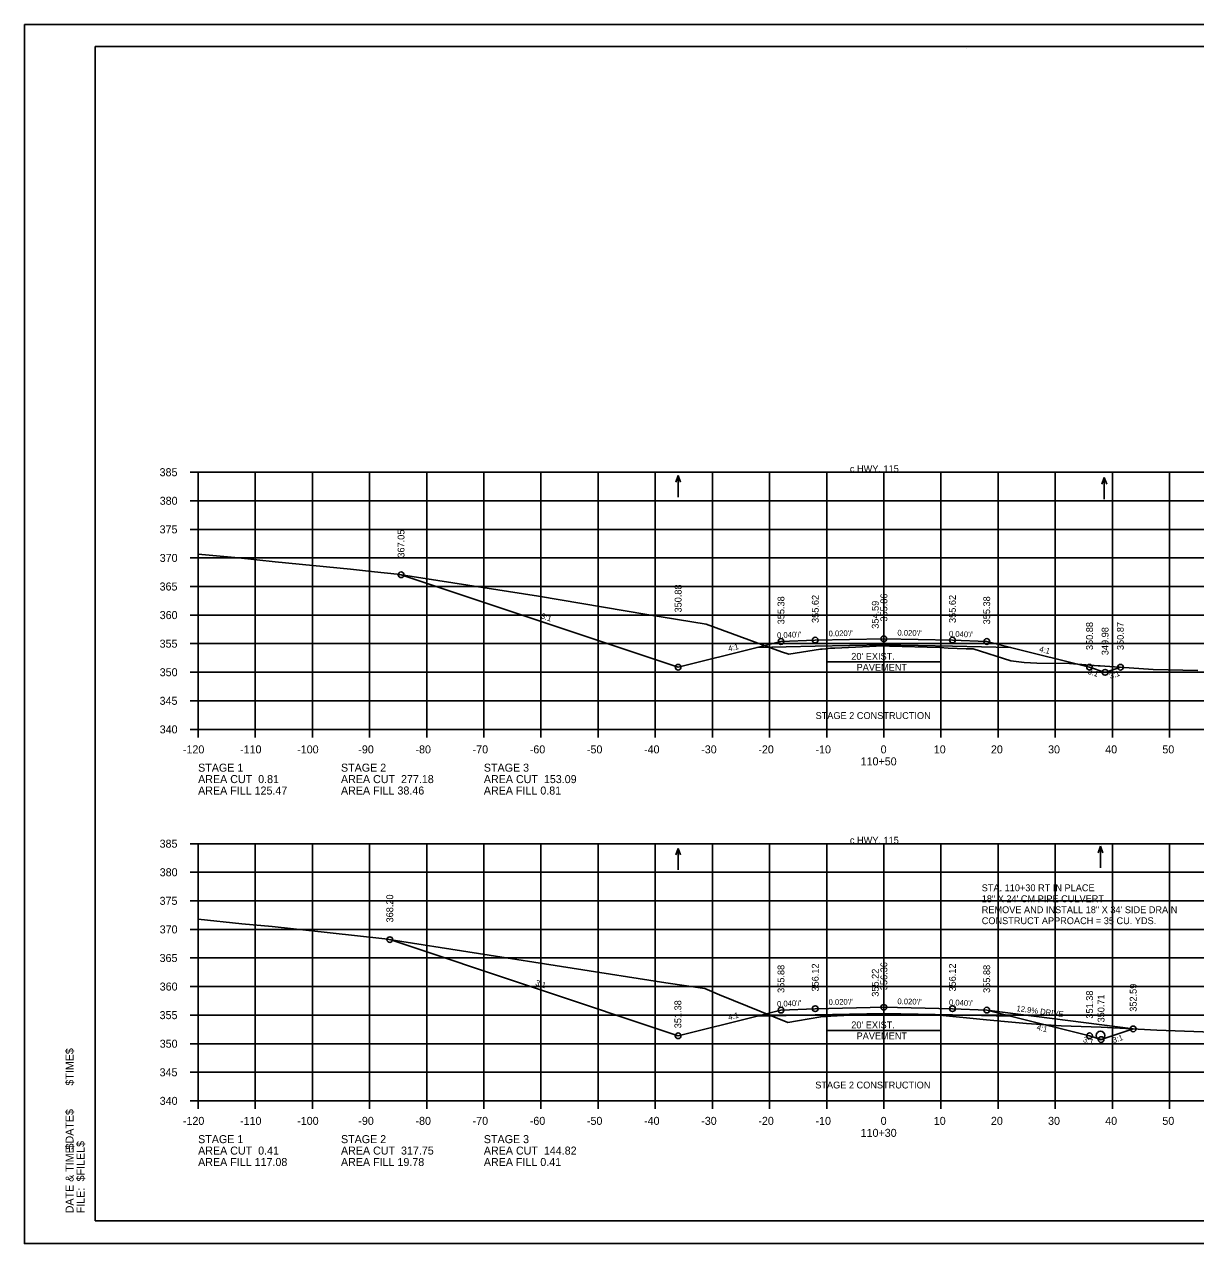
# Model space of a CAD drawing. Extents: x 1630712 to 1632516, y 782146 to 785403.
# Drawn here: x 1632182.6 to 1632387.5, y 784123.3 to 784336.6 of the extents above; entities that cross this region are included whole.
import ezdxf

# ---------------------------------------------------------------- set-up
doc = ezdxf.new("R2010")
doc.units = 0
for name, color, linetype in [('Default', 7, 'Continuous'), ('Notes', 7, 'Continuous'), ('R_Alt Surface', 7, 'Continuous'), ('R_Axis', 7, 'Continuous'), ('R_Axis Annot', 7, 'Continuous'), ('R_Border', 7, 'Continuous'), ('R_Culvert', 7, 'Continuous'), ('R_Culvert Annot', 7, 'Continuous'), ('R_Culvert Disable', 7, 'Continuous'), ('R_Exist Surface', 7, 'Continuous'), ('R_Fin Surface', 7, 'Continuous'), ('R_Grid', 7, 'Continuous'), ('R_No Plot', 7, 'Continuous'), ('R_Water Annot', 7, 'Continuous'), ('R_Xsect Elev', 7, 'Continuous'), ('R_Xsect Slope', 7, 'Continuous')]:
    doc.layers.add(name, color=color, linetype=linetype)

msp = doc.modelspace()

# ---------------------------------------------------------------- linework, layer by layer
at = {"layer": 'Notes'}
for p, q in [((1632322.96, 784223.41), (1632322.96, 784226.81)), ((1632322.96, 784225.11), (1632342.96, 784225.11)), ((1632342.96, 784223.41), (1632342.96, 784226.81)), ((1632322.96, 784158.92), (1632322.96, 784162.32)), ((1632342.96, 784158.92), (1632342.96, 784162.32)), ((1632322.96, 784160.62), (1632342.96, 784160.62))]:
    msp.add_line(p, q, dxfattribs=at)
at = {"layer": 'R_Alt Surface'}
for points in [[(1632310.78, 784227.63), (1632320.96, 784227.83), (1632332.96, 784228.07), (1632344.96, 784227.83), (1632355.15, 784227.63)], [(1632310.78, 784163.13), (1632320.96, 784163.33), (1632332.96, 784163.57), (1632344.96, 784163.33), (1632355.15, 784163.13)]]:
    msp.add_lwpolyline(points, dxfattribs=at)
at = {"layer": 'R_Axis'}
for p, q in [((1632211.56, 784258.29), (1632212.96, 784258.29)), ((1632212.96, 784213.29), (1632212.96, 784258.29)), ((1632211.56, 784253.29), (1632212.96, 784253.29)), ((1632211.56, 784248.29), (1632212.96, 784248.29)), ((1632211.56, 784243.29), (1632212.96, 784243.29)), ((1632211.56, 784238.29), (1632212.96, 784238.29)), ((1632211.56, 784233.29), (1632212.96, 784233.29)), ((1632211.56, 784228.29), (1632212.96, 784228.29)), ((1632211.56, 784223.29), (1632212.96, 784223.29)), ((1632211.56, 784218.29), (1632212.96, 784218.29)), ((1632211.56, 784213.29), (1632212.96, 784213.29)), ((1632212.96, 784213.29), (1632492.96, 784213.29)), ((1632212.96, 784211.89), (1632212.96, 784213.29)), ((1632222.96, 784211.89), (1632222.96, 784213.29)), ((1632232.96, 784211.89), (1632232.96, 784213.29)), ((1632242.96, 784211.89), (1632242.96, 784213.29)), ((1632252.96, 784211.89), (1632252.96, 784213.29)), ((1632262.96, 784211.89), (1632262.96, 784213.29)), ((1632272.96, 784211.89), (1632272.96, 784213.29)), ((1632282.96, 784211.89), (1632282.96, 784213.29)), ((1632292.96, 784211.89), (1632292.96, 784213.29)), ((1632302.96, 784211.89), (1632302.96, 784213.29)), ((1632312.96, 784211.89), (1632312.96, 784213.29)), ((1632322.96, 784211.89), (1632322.96, 784213.29)), ((1632332.96, 784211.89), (1632332.96, 784213.29)), ((1632342.96, 784211.89), (1632342.96, 784213.29)), ((1632352.96, 784211.89), (1632352.96, 784213.29)), ((1632362.96, 784211.89), (1632362.96, 784213.29)), ((1632372.96, 784211.89), (1632372.96, 784213.29)), ((1632382.96, 784211.89), (1632382.96, 784213.29)), ((1632211.56, 784193.29), (1632212.96, 784193.29)), ((1632212.96, 784148.29), (1632212.96, 784193.29)), ((1632211.56, 784188.29), (1632212.96, 784188.29)), ((1632211.56, 784183.29), (1632212.96, 784183.29)), ((1632211.56, 784178.29), (1632212.96, 784178.29)), ((1632211.56, 784173.29), (1632212.96, 784173.29)), ((1632211.56, 784168.29), (1632212.96, 784168.29)), ((1632211.56, 784163.29), (1632212.96, 784163.29)), ((1632211.56, 784158.29), (1632212.96, 784158.29)), ((1632211.56, 784153.29), (1632212.96, 784153.29)), ((1632211.56, 784148.29), (1632212.96, 784148.29)), ((1632212.96, 784148.29), (1632492.96, 784148.29)), ((1632212.96, 784146.89), (1632212.96, 784148.29)), ((1632222.96, 784146.89), (1632222.96, 784148.29)), ((1632232.96, 784146.89), (1632232.96, 784148.29)), ((1632242.96, 784146.89), (1632242.96, 784148.29)), ((1632252.96, 784146.89), (1632252.96, 784148.29)), ((1632262.96, 784146.89), (1632262.96, 784148.29)), ((1632272.96, 784146.89), (1632272.96, 784148.29)), ((1632282.96, 784146.89), (1632282.96, 784148.29)), ((1632292.96, 784146.89), (1632292.96, 784148.29)), ((1632302.96, 784146.89), (1632302.96, 784148.29)), ((1632312.96, 784146.89), (1632312.96, 784148.29)), ((1632322.96, 784146.89), (1632322.96, 784148.29)), ((1632332.96, 784146.89), (1632332.96, 784148.29)), ((1632342.96, 784146.89), (1632342.96, 784148.29)), ((1632352.96, 784146.89), (1632352.96, 784148.29)), ((1632362.96, 784146.89), (1632362.96, 784148.29)), ((1632372.96, 784146.89), (1632372.96, 784148.29)), ((1632382.96, 784146.89), (1632382.96, 784148.29))]:
    msp.add_line(p, q, dxfattribs=at)
at = {"layer": 'R_Border'}
for p, q in [((1632194.96, 784332.75), (1632511.14, 784332.75)), ((1632194.96, 784127.29), (1632194.96, 784332.75)), ((1632347.48, 784332.49), (1632347.48, 784332.49)), ((1632347.48, 784332.49), (1632347.48, 784332.49)), ((1632511.14, 784127.29), (1632194.96, 784127.29))]:
    msp.add_line(p, q, dxfattribs=at)
at = {"layer": 'R_Culvert'}
for radius in [0.755, 0.75]:
    msp.add_circle((1632370.89, 784159.74), radius, dxfattribs=at)
at = {"layer": 'R_Culvert Disable'}
for radius in [0.755, 0.75]:
    msp.add_circle((1632370.89, 784159.74), radius, dxfattribs=at)
at = {"layer": 'R_Exist Surface'}
for points in [[(1632212.96, 784243.96), (1632220.03, 784243.28), (1632226.44, 784242.58), (1632239.62, 784241.33), (1632243.82, 784240.88), (1632247.81, 784240.44), (1632272.55, 784236.59), (1632291.5, 784233.39), (1632301.87, 784231.7), (1632315.07, 784226.86), (1632316.35, 784226.44), (1632321.88, 784227.3), (1632322.09, 784227.34), (1632322.17, 784227.35), (1632322.78, 784227.4), (1632323.63, 784227.49), (1632324.39, 784227.52), (1632332.83, 784227.89), (1632333.92, 784227.86), (1632342.73, 784227.64), (1632344.19, 784227.51), (1632347.35, 784227.39), (1632348.61, 784227.36), (1632355.18, 784225.3), (1632357.52, 784224.99), (1632359.73, 784224.88), (1632365.43, 784224.83), (1632370.45, 784224.42), (1632370.58, 784224.42), (1632370.79, 784224.41), (1632380.08, 784223.79), (1632387.91, 784223.59)], [(1632212.96, 784180.11), (1632220.61, 784179.28), (1632225.91, 784178.77), (1632236.04, 784177.67), (1632245.66, 784176.63), (1632294.82, 784168.97), (1632301.61, 784167.96), (1632304.18, 784166.85), (1632316.14, 784161.99), (1632317.87, 784162.31), (1632321.92, 784163), (1632322.78, 784163.06), (1632323.66, 784163.13), (1632327.07, 784163.28), (1632332.89, 784163.52), (1632339.02, 784163.36), (1632342.72, 784163.27), (1632350.92, 784162.44), (1632354.69, 784162.12), (1632357.9, 784161.85), (1632363.99, 784161.44), (1632370.98, 784161.16), (1632380.71, 784160.67), (1632390.39, 784160.33)]]:
    msp.add_lwpolyline(points, dxfattribs=at)
at = {"layer": 'R_Fin Surface'}
msp.add_line((1632350.96, 784164.18), (1632376.6, 784160.88), dxfattribs=at)
for points in [[(1632248.47, 784240.34), (1632296.96, 784224.17), (1632310.78, 784227.63), (1632314.96, 784228.67), (1632320.96, 784228.91), (1632332.96, 784229.15), (1632344.96, 784228.91), (1632350.96, 784228.67), (1632355.15, 784227.63), (1632368.96, 784224.17), (1632371.67, 784223.27), (1632374.35, 784224.17)], [(1632246.5, 784176.5), (1632296.96, 784159.68), (1632310.78, 784163.13), (1632314.96, 784164.18), (1632320.96, 784164.42), (1632332.96, 784164.66), (1632344.96, 784164.42), (1632350.96, 784164.18), (1632355.15, 784163.13), (1632368.96, 784159.68), (1632370.97, 784159.01), (1632376.6, 784160.88)]]:
    msp.add_lwpolyline(points, dxfattribs=at)
at = {"layer": 'R_Grid'}
for p, q in [((1632212.96, 784258.29), (1632492.96, 784258.29)), ((1632212.96, 784213.29), (1632212.96, 784258.29)), ((1632222.96, 784213.29), (1632222.96, 784258.29)), ((1632232.96, 784213.29), (1632232.96, 784258.29)), ((1632242.96, 784213.29), (1632242.96, 784258.29)), ((1632252.96, 784213.29), (1632252.96, 784258.29)), ((1632262.96, 784213.29), (1632262.96, 784258.29)), ((1632272.96, 784213.29), (1632272.96, 784258.29)), ((1632282.96, 784213.29), (1632282.96, 784258.29)), ((1632292.96, 784213.29), (1632292.96, 784258.29)), ((1632302.96, 784213.29), (1632302.96, 784258.29)), ((1632312.96, 784213.29), (1632312.96, 784258.29)), ((1632322.96, 784213.29), (1632322.96, 784258.29)), ((1632332.96, 784213.29), (1632332.96, 784258.29)), ((1632342.96, 784213.29), (1632342.96, 784258.29)), ((1632352.96, 784213.29), (1632352.96, 784258.29)), ((1632362.96, 784213.29), (1632362.96, 784258.29)), ((1632372.96, 784213.29), (1632372.96, 784258.29)), ((1632382.96, 784213.29), (1632382.96, 784258.29)), ((1632212.96, 784253.29), (1632492.96, 784253.29)), ((1632212.96, 784248.29), (1632492.96, 784248.29)), ((1632212.96, 784243.29), (1632492.96, 784243.29)), ((1632212.96, 784238.29), (1632492.96, 784238.29)), ((1632212.96, 784233.29), (1632492.96, 784233.29)), ((1632212.96, 784228.29), (1632492.96, 784228.29)), ((1632212.96, 784223.29), (1632492.96, 784223.29)), ((1632212.96, 784218.29), (1632492.96, 784218.29)), ((1632212.96, 784213.29), (1632492.96, 784213.29)), ((1632212.96, 784193.29), (1632492.96, 784193.29)), ((1632212.96, 784148.29), (1632212.96, 784193.29)), ((1632222.96, 784148.29), (1632222.96, 784193.29)), ((1632232.96, 784148.29), (1632232.96, 784193.29)), ((1632242.96, 784148.29), (1632242.96, 784193.29)), ((1632252.96, 784148.29), (1632252.96, 784193.29)), ((1632262.96, 784148.29), (1632262.96, 784193.29)), ((1632272.96, 784148.29), (1632272.96, 784193.29)), ((1632282.96, 784148.29), (1632282.96, 784193.29)), ((1632292.96, 784148.29), (1632292.96, 784193.29)), ((1632302.96, 784148.29), (1632302.96, 784193.29)), ((1632312.96, 784148.29), (1632312.96, 784193.29)), ((1632322.96, 784148.29), (1632322.96, 784193.29)), ((1632332.96, 784148.29), (1632332.96, 784193.29)), ((1632342.96, 784148.29), (1632342.96, 784193.29)), ((1632352.96, 784148.29), (1632352.96, 784193.29)), ((1632362.96, 784148.29), (1632362.96, 784193.29)), ((1632372.96, 784148.29), (1632372.96, 784193.29)), ((1632382.96, 784148.29), (1632382.96, 784193.29)), ((1632212.96, 784188.29), (1632492.96, 784188.29)), ((1632212.96, 784183.29), (1632492.96, 784183.29)), ((1632212.96, 784178.29), (1632492.96, 784178.29)), ((1632212.96, 784173.29), (1632492.96, 784173.29)), ((1632212.96, 784168.29), (1632492.96, 784168.29)), ((1632212.96, 784163.29), (1632492.96, 784163.29)), ((1632212.96, 784158.29), (1632492.96, 784158.29)), ((1632212.96, 784153.29), (1632492.96, 784153.29)), ((1632212.96, 784148.29), (1632492.96, 784148.29))]:
    msp.add_line(p, q, dxfattribs=at)
at = {"layer": 'R_No Plot'}
for p, q in [((1632182.56, 784336.65), (1632515.9, 784336.65)), ((1632182.56, 784123.31), (1632515.9, 784123.31))]:
    msp.add_line(p, q, dxfattribs=at)
msp.add_lwpolyline([(1632182.56, 784336.65), (1632515.9, 784336.65), (1632515.9, 784123.31), (1632182.56, 784123.31)], close=True, dxfattribs=at)
for centre in [(1632248.47, 784240.34), (1632314.96, 784228.67), (1632320.96, 784228.91), (1632332.96, 784229.15), (1632344.96, 784228.91), (1632350.96, 784228.67), (1632296.96, 784224.17), (1632296.96, 784224.17), (1632368.96, 784224.17), (1632371.67, 784223.27), (1632374.35, 784224.17), (1632246.5, 784176.5), (1632332.96, 784164.66), (1632314.96, 784164.18), (1632320.96, 784164.42), (1632344.96, 784164.42), (1632350.96, 784164.18), (1632376.6, 784160.88), (1632296.96, 784159.68), (1632296.96, 784159.68), (1632368.96, 784159.68), (1632370.97, 784159.01)]:
    msp.add_circle(centre, 0.5, dxfattribs=at)
at = {"layer": 'R_Water Annot'}
for p, q in [((1632296.96, 784257.71), (1632296.54, 784256.56)), ((1632296.96, 784253.94), (1632296.96, 784257.71)), ((1632296.96, 784257.71), (1632297.38, 784256.56)), ((1632371.54, 784257.35), (1632371.12, 784256.19)), ((1632371.54, 784253.58), (1632371.54, 784257.35)), ((1632371.54, 784257.35), (1632371.96, 784256.19)), ((1632370.86, 784192.84), (1632370.44, 784191.68)), ((1632370.86, 784189.07), (1632370.86, 784192.84)), ((1632370.86, 784192.84), (1632371.28, 784191.68)), ((1632296.96, 784192.47), (1632296.54, 784191.32)), ((1632296.96, 784188.7), (1632296.96, 784192.47)), ((1632296.96, 784192.47), (1632297.38, 784191.32))]:
    msp.add_line(p, q, dxfattribs=at)

# ---------------------------------------------------------------- texts
at = {"layer": 'Default'}
for s, height, p in [('$TIME$', 1.397, (1632191.16, 784150.96)), ('$DATE$', 1.397, (1632191.16, 784139.79)), ('DATE & TIME:', 1.3968, (1632191.16, 784128.62)), ('$FILEL$', 1.397, (1632193.08, 784134.2)), ('FILE: ', 1.397, (1632193.08, 784128.62))]:
    msp.add_text(s, height=height, rotation=90, dxfattribs=at).set_placement(p)
at = {"layer": 'Notes'}
for s, p in [('c HWY. 115', (1632327.02, 784258.29)), ("20' EXIST.", (1632327.26, 784225.47)), ('PAVEMENT', (1632328.19, 784223.55)), ('STAGE 2 CONSTRUCTION', (1632321.01, 784215.11)), ('c HWY. 115', (1632327.02, 784193.29)), ("20' EXIST.", (1632327.26, 784160.98)), ('PAVEMENT', (1632328.19, 784159.06)), ('STAGE 2 CONSTRUCTION', (1632320.96, 784150.46))]:
    msp.add_text(s, height=1.2, dxfattribs=at).set_placement(p)
msp.add_text('12.9% DRIVE', height=1, rotation=352.6734, dxfattribs=at).set_placement((1632356.13, 784163.99))
at = {"layer": 'R_Axis'}
for p in [(1632212.96, 784213.29), (1632212.96, 784148.29)]:
    msp.add_text('-', height=0.0001, dxfattribs=at).set_placement(p)
at = {"layer": 'R_Axis Annot'}
for s, p in [('385', (1632206.22, 784257.59)), ('380', (1632206.24, 784252.59)), ('375', (1632206.22, 784247.59)), ('370', (1632206.24, 784242.59)), ('365', (1632206.22, 784237.59)), ('360', (1632206.24, 784232.59)), ('355', (1632206.22, 784227.59)), ('350', (1632206.24, 784222.59)), ('345', (1632206.22, 784217.59)), ('340', (1632206.24, 784212.59)), ('-120', (1632210.3, 784209.09)), ('-110', (1632220.3, 784209.09)), ('-100', (1632230.3, 784209.09)), ('-90', (1632241, 784209.09)), ('-80', (1632251, 784209.09)), ('-70', (1632261, 784209.09)), ('-60', (1632271, 784209.09)), ('-50', (1632281, 784209.09)), ('-40', (1632291, 784209.09)), ('-30', (1632301, 784209.09)), ('-20', (1632311, 784209.09)), ('-10', (1632321, 784209.09)), ('0', (1632332.4, 784209.09)), ('10', (1632341.7, 784209.09)), ('20', (1632351.7, 784209.09)), ('30', (1632361.7, 784209.09)), ('40', (1632371.7, 784209.09)), ('50', (1632381.7, 784209.09)), ('110+50', (1632328.9, 784206.99)), ('STAGE 1', (1632212.96, 784205.89)), ('STAGE 2', (1632237.96, 784205.89)), ('STAGE 3', (1632262.96, 784205.89)), ('AREA CUT  0.81', (1632212.96, 784203.89)), ('AREA CUT  277.18', (1632237.96, 784203.89)), ('AREA CUT  153.09', (1632262.96, 784203.89)), ('AREA FILL 125.47', (1632212.96, 784201.89)), ('AREA FILL 38.46', (1632237.96, 784201.89)), ('AREA FILL 0.81', (1632262.96, 784201.89)), ('385', (1632206.22, 784192.59)), ('380', (1632206.24, 784187.59)), ('375', (1632206.22, 784182.59)), ('370', (1632206.24, 784177.59)), ('365', (1632206.22, 784172.59)), ('360', (1632206.24, 784167.59)), ('355', (1632206.22, 784162.59)), ('350', (1632206.24, 784157.59)), ('345', (1632206.22, 784152.59)), ('340', (1632206.24, 784147.59)), ('-120', (1632210.3, 784144.09)), ('-110', (1632220.3, 784144.09)), ('-100', (1632230.3, 784144.09)), ('-90', (1632241, 784144.09)), ('-80', (1632251, 784144.09)), ('-70', (1632261, 784144.09)), ('-60', (1632271, 784144.09)), ('-50', (1632281, 784144.09)), ('-40', (1632291, 784144.09)), ('-30', (1632301, 784144.09)), ('-20', (1632311, 784144.09)), ('-10', (1632321, 784144.09)), ('0', (1632332.4, 784144.09)), ('10', (1632341.7, 784144.09)), ('20', (1632351.7, 784144.09)), ('30', (1632361.7, 784144.09)), ('40', (1632371.7, 784144.09)), ('50', (1632381.7, 784144.09)), ('STAGE 1', (1632212.96, 784140.89)), ('STAGE 2', (1632237.96, 784140.89)), ('STAGE 3', (1632262.96, 784140.89)), ('110+30', (1632328.9, 784141.99)), ('AREA CUT  0.41', (1632212.96, 784138.89)), ('AREA CUT  317.75', (1632237.96, 784138.89)), ('AREA CUT  144.82', (1632262.96, 784138.89)), ('AREA FILL 117.08', (1632212.96, 784136.89)), ('AREA FILL 19.78', (1632237.96, 784136.89)), ('AREA FILL 0.41', (1632262.96, 784136.89))]:
    msp.add_text(s, height=1.4, dxfattribs=at).set_placement(p)
at = {"layer": 'R_Culvert Annot'}
for s, p in [('STA. 110+30 RT IN PLACE', (1632350.09, 784184.97)), ('18" X 24\' CM PIPE CULVERT', (1632350.09, 784183.05)), ('REMOVE AND INSTALL 18" X 34\' SIDE DRAIN', (1632350.09, 784181.13)), ('CONSTRUCT APPROACH = 35 CU. YDS.', (1632350.09, 784179.21))]:
    msp.add_text(s, height=1.2, dxfattribs=at).set_placement(p)
at = {"layer": 'R_Xsect Elev'}
for s, p in [('367.05', (1632249.07, 784243.34)), ('350.88', (1632297.56, 784233.74)), ('355.38', (1632315.56, 784231.67)), ('355.62', (1632321.56, 784231.91)), ('354.59', (1632332.06, 784230.89)), ('355.86', (1632333.56, 784232.15)), ('355.62', (1632345.56, 784231.91)), ('355.38', (1632351.56, 784231.67)), ('350.88', (1632369.56, 784227.17)), ('350.87', (1632374.95, 784227.17)), ('349.98', (1632372.27, 784226.27)), ('368.20', (1632247.1, 784179.5)), ('355.88', (1632315.56, 784167.18)), ('356.12', (1632321.56, 784167.42)), ('356.36', (1632333.56, 784167.66)), ('356.12', (1632345.56, 784167.42)), ('355.88', (1632351.56, 784167.18)), ('355.22', (1632332.06, 784166.51)), ('351.38', (1632369.56, 784162.68)), ('352.59', (1632377.2, 784163.88)), ('351.38', (1632297.52, 784160.99)), ('350.71', (1632371.57, 784162.01))]:
    msp.add_text(s, height=1.2, rotation=90, dxfattribs=at).set_placement(p)
at = {"layer": 'R_Xsect Slope'}
for s, rotation, p in [('3:1', 341.5651, (1632272.87, 784232.73)), ("0.040'/'", 2.2906, (1632314.29, 784229.25)), ("0.020'/'", 1.1458, (1632323.3, 784229.56)), ("0.020'/'", 358.8542, (1632335.33, 784229.71)), ("0.040'/'", 357.7094, (1632344.34, 784229.54)), ('4:1', 14.0362, (1632305.84, 784226.91)), ('4:1', 345.9638, (1632360.09, 784226.91)), ('3:1', 341.5651, (1632368.55, 784223.03)), ('3:1', 18.4349, (1632372.6, 784222.12)), ('3:1', 341.5651, (1632271.89, 784168.56)), ("0.040'/'", 2.2906, (1632314.29, 784164.75)), ("0.020'/'", 1.1458, (1632323.3, 784165.06)), ("0.020'/'", 358.8542, (1632335.33, 784165.21)), ("0.040'/'", 357.7094, (1632344.34, 784165.04)), ('4:1', 14.0362, (1632305.84, 784162.41)), ('4:1', 345.9638, (1632359.64, 784160.73)), ('3:1', 341.5651, (1632367.72, 784158.64)), ('3:1', 18.4349, (1632373.16, 784158.39))]:
    msp.add_text(s, height=1, rotation=rotation, dxfattribs=at).set_placement(p)

doc.saveas('drawing.dxf')
